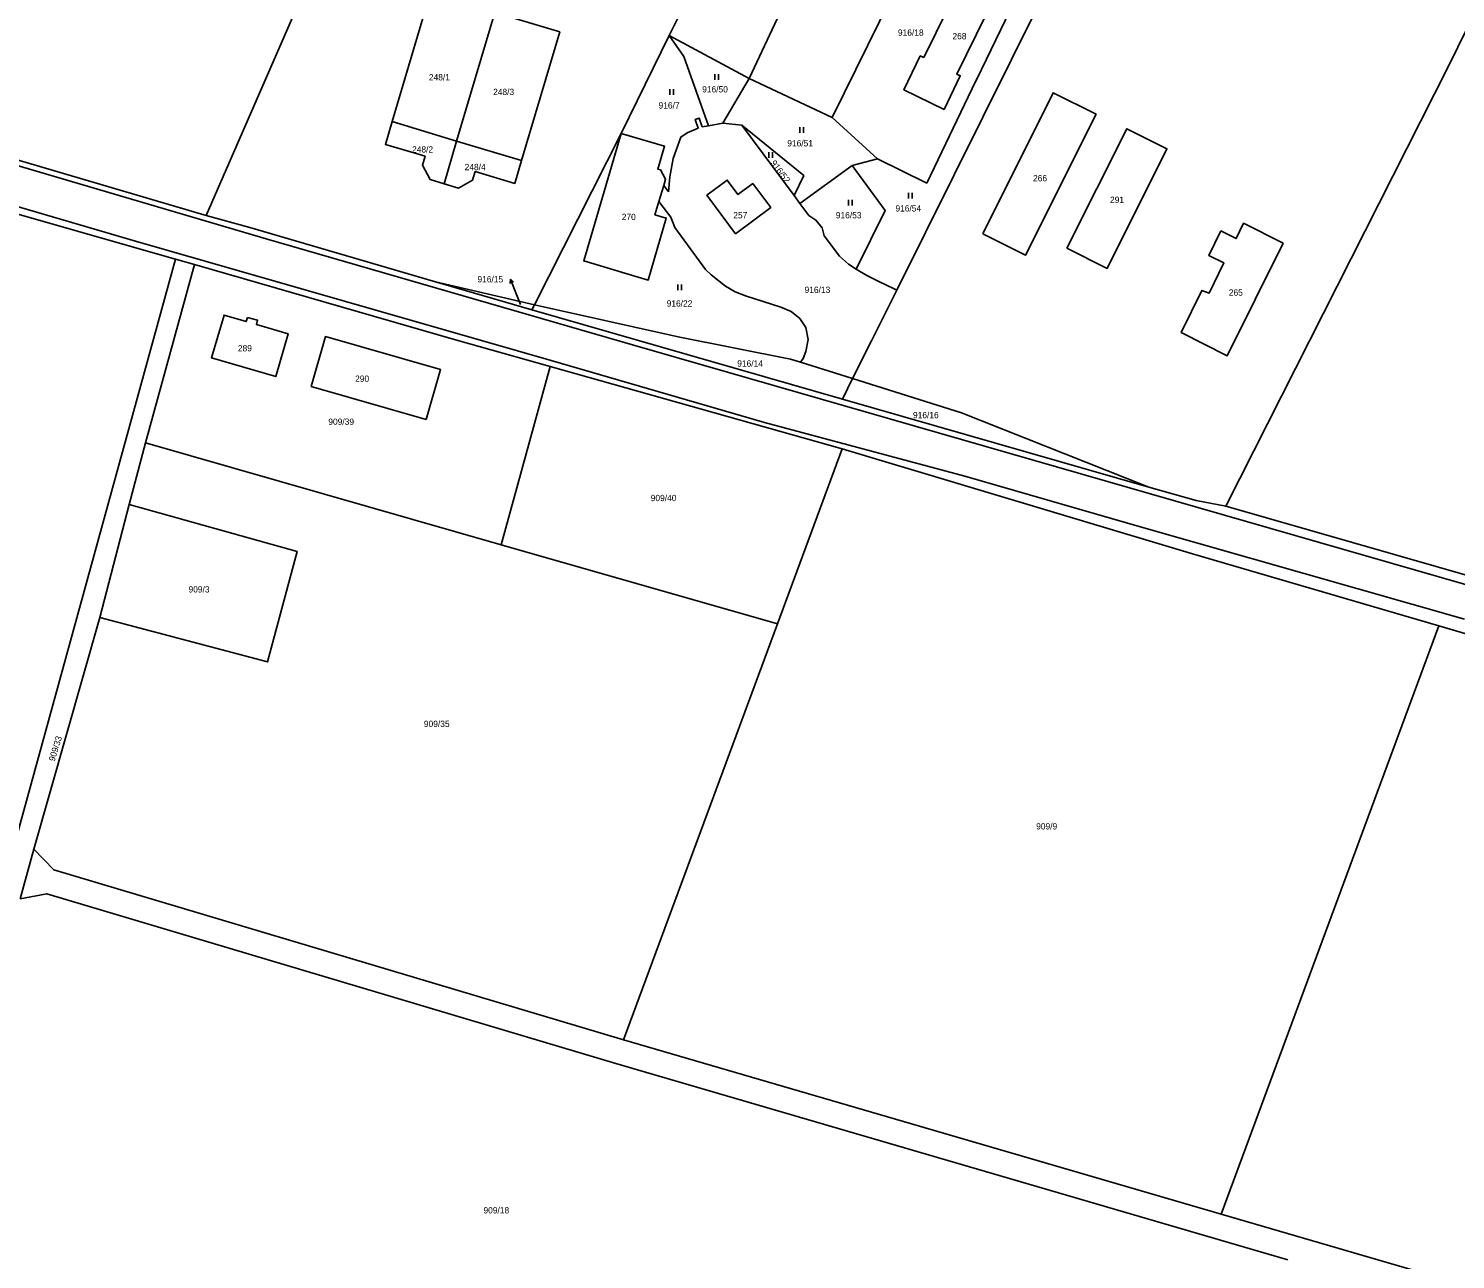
# Model space of a CAD drawing. Extents: x -751333 to -746055, y -1133395 to -1129777.
# Drawn here: x -750408.5 to -750022.6, y -1131564.4 to -1131231.7 of the extents above; entities that cross this region are included whole.
import ezdxf

# ---------------------------------------------------------------- set-up
doc = ezdxf.new("R2010")
doc.units = 0
for name, color, linetype in [('Hranice parcel', 7, 'Continuous'), ('Parcelní čísla', 7, 'Continuous'), ('Pop  PČ popisy', 7, 'Continuous'), ('Vnitřní kresba', 7, 'Continuous'), ('Značky kultur', 7, 'Continuous')]:
    doc.layers.add(name, color=color, linetype=linetype)

msp = doc.modelspace()

# ---------------------------------------------------------------- linework, layer by layer
at = {"layer": 'Hranice parcel'}
for p, q in [((-750213.6, -1131245.21), (-750183.36, -1131180.54)), ((-750235.23, -1131233.64), (-750213.06, -1131188.66)), ((-750324.56, -1131199.94), (-750360.45, -1131282.22)), ((-750191.14, -1131255.75), (-750164.85, -1131202.13)), ((-750292.72, -1131262.14), (-750282.4, -1131227.41)), ((-750528.14, -1131233.04), (-750360.45, -1131282.22)), ((-750248.26, -1131260.08), (-750235.23, -1131233.64)), ((-750213.6, -1131245.21), (-750235.23, -1131233.64)), ((-750231.31, -1131239.24), (-750235.23, -1131233.64)), ((-750224.57, -1131257.99), (-750231.31, -1131239.24)), ((-750220.69, -1131257.3), (-750213.6, -1131245.21)), ((-750191.14, -1131255.75), (-750213.6, -1131245.21)), ((-750310.14, -1131256.86), (-750292.72, -1131262.14)), ((-750220.69, -1131257.3), (-750224.57, -1131257.99)), ((-750215.6, -1131257.81), (-750220.69, -1131257.3)), ((-750201.48, -1131276.85), (-750215.6, -1131257.81)), ((-750191.14, -1131255.75), (-750178.9, -1131266.92)), ((-750296.07, -1131273.69), (-750292.72, -1131262.14)), ((-750292.72, -1131262.14), (-750275.17, -1131267.37)), ((-750271.68, -1131306.39), (-750248.26, -1131260.08)), ((-750199.88, -1131279.01), (-750185.76, -1131268.74)), ((-750185.76, -1131268.74), (-750178.9, -1131266.92)), ((-750238.02, -1131278.51), (-750236.72, -1131274.17)), ((-750236.72, -1131274.17), (-750235.44, -1131275.83)), ((-750368.77, -1131294.03), (-750429.73, -1131276.7)), ((-750199.88, -1131279.01), (-750201.48, -1131276.85)), ((-750238.02, -1131278.51), (-750234.83, -1131282.68)), ((-750376.86, -1131343.72), (-750363.58, -1131295.52)), ((-750363.58, -1131295.52), (-750368.77, -1131294.03)), ((-750181.78, -1131298.5), (-750184.65, -1131296.75)), ((-750298.46, -1131300.2), (-750271.68, -1131306.39)), ((-750298.46, -1131300.2), (-750272.39, -1131307.79)), ((-750272.39, -1131307.79), (-750271.68, -1131306.39)), ((-750272.39, -1131307.79), (-750188.4, -1131331.9)), ((-750232.83, -1131315.05), (-750271.68, -1131306.39)), ((-750280.72, -1131371.25), (-750267.44, -1131323.05)), ((-750267.44, -1131323.05), (-750188.41, -1131345.3)), ((-750199.74, -1131321.89), (-750185.65, -1131326.3)), ((-750188.4, -1131331.9), (-750185.65, -1131326.3)), ((-750185.65, -1131326.3), (-750156.2, -1131335.62)), ((-750188.4, -1131331.9), (-750105.48, -1131355.7)), ((-750156.2, -1131335.62), (-750105.48, -1131355.7)), ((-750381.31, -1131360.4), (-750376.86, -1131343.72)), ((-750280.72, -1131371.25), (-750376.86, -1131343.72)), ((-750205.95, -1131392.66), (-750188.41, -1131345.3)), ((-750381.31, -1131360.4), (-750389.25, -1131390.88)), ((-750205.95, -1131392.66), (-750280.72, -1131371.25)), ((-750407.11, -1131453.55), (-750389.25, -1131390.88)), ((-750247.56, -1131505.04), (-750205.95, -1131392.66)), ((-750027.07, -1131393.19), (-750085.94, -1131552.16)), ((-750410.8, -1131466.96), (-750407.11, -1131453.55)), ((-750085.94, -1131552.16), (-750247.56, -1131505.04)), ((-749969.59, -1131586.07), (-750085.94, -1131552.16))]:
    msp.add_line(p, q, dxfattribs=at)
for points in [[(-750084.66, -1131360.85), (-750024.43, -1131241.89), (-749966.16, -1131123.14)], [(-750178.9, -1131266.92), (-750165.58, -1131273.52), (-750152.27, -1131245.87), (-750152.05, -1131245.42), (-750137.8, -1131215.82)], [(-750166.39, -1131239.57), (-750167.34, -1131239.11), (-750171.77, -1131248.26), (-750160.9, -1131253.58), (-750156.52, -1131244.49), (-750157.47, -1131244.03), (-750144.17, -1131217.03), (-750153.14, -1131212.62), (-750166.39, -1131239.57)], [(-750131.95, -1131218.45), (-750134.94, -1131224.54), (-750173.68, -1131302.46)], [(-750282.4, -1131227.41), (-750299.84, -1131222.2), (-750310.14, -1131256.86)], [(-750275.17, -1131267.37), (-750264.83, -1131232.64), (-750282.4, -1131227.41)], [(-750150.44, -1131287.18), (-750138.87, -1131292.97), (-750119.76, -1131254.89), (-750131.39, -1131249.08), (-750150.44, -1131287.18)], [(-750310.14, -1131256.86), (-750311.97, -1131263.05), (-750301.25, -1131266.23), (-750301.96, -1131268.62), (-750299.91, -1131272.53), (-750296.07, -1131273.69)], [(-750235.44, -1131275.83), (-750235.07, -1131271.78), (-750234.17, -1131266.81), (-750232.12, -1131261.08), (-750230.39, -1131259.96), (-750227.42, -1131258.67), (-750228.21, -1131256.31), (-750227.09, -1131255.91), (-750226.29, -1131258.29), (-750224.57, -1131257.99)], [(-750215.6, -1131257.81), (-750198.84, -1131271.46), (-750201.48, -1131276.85)], [(-750127.66, -1131291.13), (-750116.79, -1131296.55), (-750100.62, -1131264.23), (-750111.49, -1131258.8), (-750127.66, -1131291.13)], [(-750248.26, -1131260.08), (-750258.33, -1131294.52), (-750240.89, -1131299.71), (-750236.02, -1131282.98), (-750239.08, -1131282.06), (-750238.02, -1131278.51)], [(-750236.72, -1131274.17), (-750236.19, -1131272.42), (-750237.56, -1131269.94), (-750238.31, -1131269.72), (-750236.48, -1131263.55), (-750248.26, -1131260.08)], [(-750296.07, -1131273.69), (-750292.22, -1131274.84), (-750288.42, -1131272.75), (-750287.72, -1131270.38), (-750277.01, -1131273.57), (-750275.17, -1131267.37)], [(-750185.76, -1131268.74), (-750176.85, -1131280.89), (-750184.65, -1131296.75)], [(-750217.32, -1131287.2), (-750207.78, -1131280.08), (-750212.64, -1131273.63), (-750216.63, -1131276.61), (-750219.52, -1131272.67), (-750225.03, -1131276.8), (-750217.32, -1131287.2)], [(-750184.65, -1131296.75), (-750186.77, -1131295.46), (-750189.14, -1131293.25), (-750193.36, -1131287.8), (-750193.84, -1131285.62), (-750195.57, -1131283.49), (-750197.49, -1131282.23), (-750199.88, -1131279.01)], [(-750360.45, -1131282.22), (-750348.62, -1131285.5), (-750298.46, -1131300.2)], [(-750234.83, -1131282.68), (-750233.72, -1131285.51), (-750225.39, -1131296.89), (-750223.88, -1131298.31), (-750220.03, -1131301.39), (-750217.4, -1131302.86), (-750214.6, -1131303.99), (-750205.02, -1131307.02), (-750202.29, -1131308.25), (-750199.92, -1131310.11), (-750198.25, -1131312.57), (-750197.69, -1131315.75), (-750198.32, -1131319.01), (-750198.97, -1131320.91), (-750199.74, -1131321.89)], [(-750069.14, -1131289.7), (-750079.88, -1131284.36), (-750081.92, -1131288.48), (-750086.03, -1131286.44), (-750089.32, -1131293.05), (-750085.22, -1131295.1), (-750089.22, -1131303.28), (-750091.14, -1131302.52), (-750096.78, -1131313.88), (-750084.29, -1131320.16), (-750069.14, -1131289.7)], [(-750443.23, -1131564.35), (-750407.78, -1131435.86), (-750368.77, -1131294.03)], [(-750363.58, -1131295.52), (-750293.03, -1131315.85), (-750267.44, -1131323.05)], [(-750173.68, -1131302.46), (-750177.38, -1131300.65), (-750177.83, -1131300.43), (-750181.78, -1131298.5)], [(-750173.68, -1131302.46), (-750180.41, -1131315.97), (-750185.65, -1131326.3)], [(-750349.29, -1131309.79), (-750346.58, -1131310.57), (-750346.89, -1131311.71), (-750338.31, -1131314.21), (-750341.64, -1131325.78), (-750358.98, -1131320.76), (-750355.64, -1131309.19), (-750349.64, -1131310.93), (-750349.29, -1131309.79)], [(-750300.92, -1131337.38), (-750332.05, -1131328.47), (-750328.2, -1131315), (-750297.06, -1131323.92), (-750300.92, -1131337.38)], [(-750199.74, -1131321.89), (-750202.42, -1131321.06), (-750232.83, -1131315.05)], [(-750188.41, -1131345.3), (-750093.71, -1131373.73), (-750027.07, -1131393.19)], [(-750105.48, -1131355.7), (-750092.73, -1131359.32), (-750084.66, -1131360.85)], [(-750389.25, -1131390.88), (-750343.85, -1131402.94), (-750335.82, -1131373.07), (-750381.31, -1131360.4)], [(-749953.16, -1131398.66), (-749982.59, -1131390.14), (-750084.66, -1131360.85)], [(-750027.07, -1131393.19), (-749986.84, -1131404.94), (-749910.73, -1131427.13)], [(-750407.11, -1131453.55), (-750401.64, -1131459.15), (-750247.56, -1131505.04)], [(-750067.88, -1131564.53), (-750249.66, -1131511.44), (-750403.56, -1131465.6), (-750410.8, -1131466.96)]]:
    msp.add_lwpolyline(points, dxfattribs=at)
at = {"layer": 'Pop  PČ popisy'}
for p, q in [((-750278.194, -1131299.498), (-750278.283, -1131300.614)), ((-750277.07, -1131302.28), (-750278.194, -1131299.498)), ((-750278.194, -1131299.498), (-750277.355, -1131300.238)), ((-750275.43, -1131306.28), (-750277.07, -1131302.28))]:
    msp.add_line(p, q, dxfattribs=at)
at = {"layer": 'Vnitřní kresba'}
for p, q in [((-750344.21, -1131288.58), (-750506.88, -1131240.71)), ((-750379.57, -1131289.16), (-750480.64, -1131259.63)), ((-750267.13, -1131321.44), (-750379.57, -1131289.16)), ((-750245.14, -1131317.19), (-750344.21, -1131288.58)), ((-750085.67, -1131363.08), (-750245.14, -1131317.19)), ((-750209.48, -1131338.18), (-750267.13, -1131321.44)), ((-750155.3, -1131352.72), (-750209.48, -1131338.18)), ((-750106.84, -1131366.7), (-750155.3, -1131352.72)), ((-750020.17, -1131391.38), (-750106.84, -1131366.7)), ((-749959.52, -1131399.32), (-750085.67, -1131363.08))]:
    msp.add_line(p, q, dxfattribs=at)
at = {"layer": 'Značky kultur'}
for p, q in [((-750222.881, -1131245.56), (-750222.881, -1131244.06)), ((-750221.88, -1131245.56), (-750221.88, -1131244.06)), ((-750235.071, -1131249.65), (-750235.071, -1131248.15)), ((-750234.07, -1131249.65), (-750234.07, -1131248.15)), ((-750199.941, -1131259.9), (-750199.941, -1131258.4)), ((-750198.94, -1131259.9), (-750198.94, -1131258.4)), ((-750208.291, -1131266.63), (-750208.291, -1131265.13)), ((-750207.29, -1131266.63), (-750207.29, -1131265.13)), ((-750186.731, -1131279.52), (-750186.731, -1131278.02)), ((-750185.73, -1131279.52), (-750185.73, -1131278.02)), ((-750170.531, -1131277.65), (-750170.531, -1131276.15)), ((-750169.53, -1131277.65), (-750169.53, -1131276.15)), ((-750232.881, -1131302.43), (-750232.881, -1131300.93)), ((-750231.88, -1131302.43), (-750231.88, -1131300.93))]:
    msp.add_line(p, q, dxfattribs=at)

# ---------------------------------------------------------------- texts
at = {"layer": 'Parcelní čísla'}
for s, p in [('916/18', (-750173.37, -1131233.67)), ('268', (-750158.63, -1131234.64)), ('248/1', (-750300.23, -1131245.75)), ('916/50', (-750226.317, -1131249)), ('248/3', (-750282.86, -1131249.71)), ('916/7', (-750238.11, -1131253.35)), ('916/51', (-750203.297, -1131263.59)), ('248/2', (-750304.78, -1131265.24)), ('248/4', (-750290.56, -1131270.01)), ('266', (-750136.83, -1131273.03)), ('291', (-750116.015, -1131278.85)), ('270', (-750248.07, -1131283.5)), ('257', (-750217.9, -1131283.04)), ('916/53', (-750190.167, -1131283.04)), ('916/54', (-750174.047, -1131281.18)), ('916/15', (-750287.095, -1131300.35)), ('916/22', (-750235.92, -1131306.88)), ('916/13', (-750198.62, -1131303.19)), ('265', (-750083.88, -1131303.94)), ('289', (-750351.885, -1131318.99)), ('916/14', (-750216.83, -1131323.11)), ('290', (-750320.185, -1131327.22)), ('916/16', (-750169.3, -1131337.06)), ('909/39', (-750327.427, -1131338.85)), ('909/40', (-750240.23, -1131359.47)), ('909/3', (-750365.24, -1131384.16)), ('909/35', (-750301.58, -1131420.52)), ('909/9', (-750135.978, -1131448.214)), ('909/18', (-750285.477, -1131552.004))]:
    msp.add_text(s, height=1.7, dxfattribs=at).set_placement(p)
for s, rotation, p in [('916/52', 307, (-750207.914, -1131268.118)), ('909/33', 73, (-750401.467, -1131429.928))]:
    msp.add_text(s, height=1.7, rotation=rotation, dxfattribs=at).set_placement(p)

doc.saveas('drawing.dxf')
